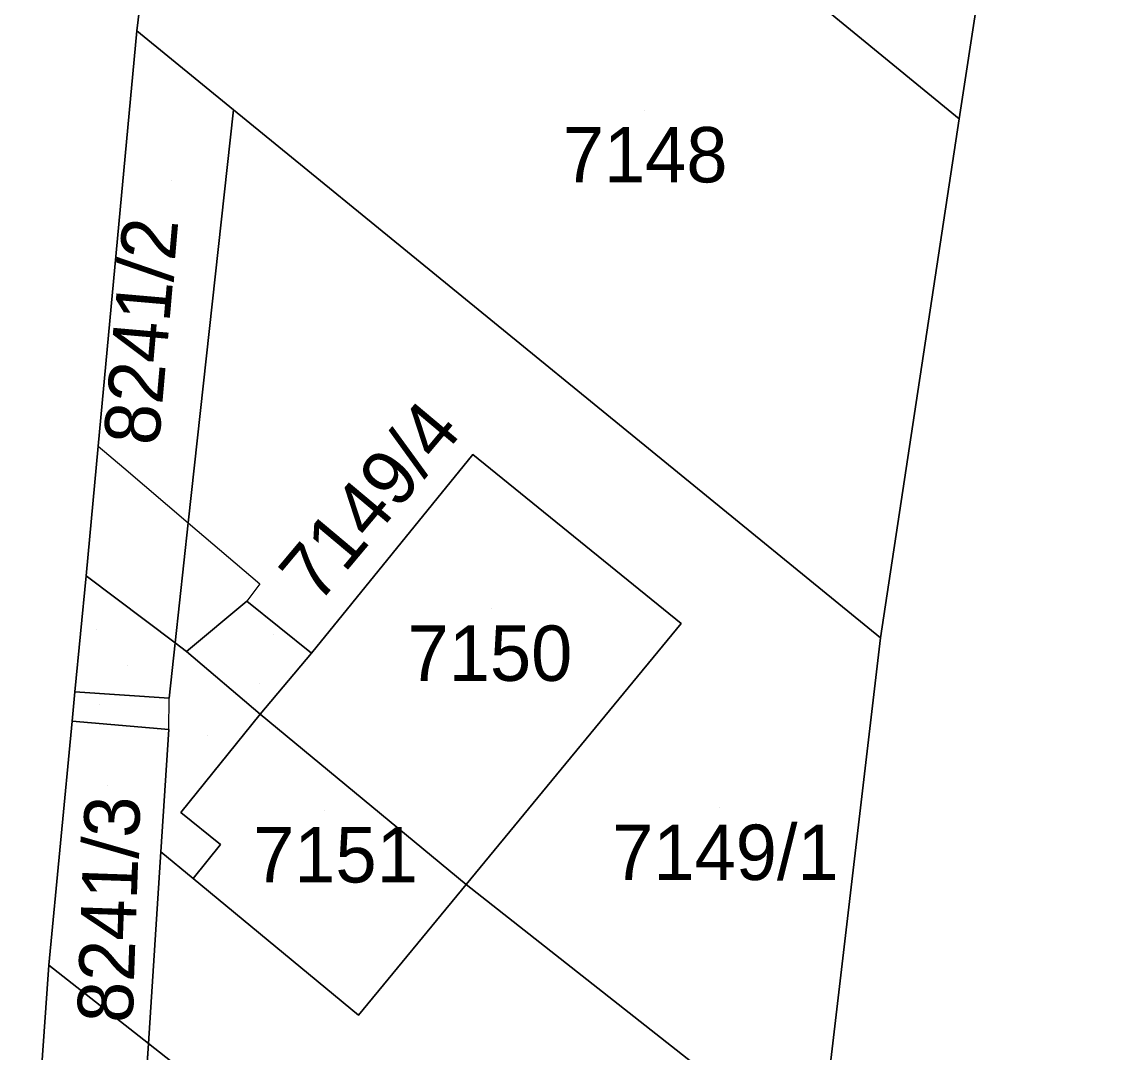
# Model space of a CAD drawing. Extents: x -266199 to -261993, y -1239047 to -1235108.
# Drawn here: x -263577.75 to -263537.93, y -1236344.71 to -1236307.48 of the extents above; entities that cross this region are included whole.
import ezdxf

# ---------------------------------------------------------------- set-up
doc = ezdxf.new("R2010")
doc.units = 0
for name, color, linetype in [('body_kn', 7, 'Continuous'), ('kladpar_druhypozemkov', 7, 'Continuous'), ('kladpar_hranice', 7, 'Continuous'), ('kladpar_parcelnecisla', 7, 'Continuous'), ('kladpar_plochy', 7, 'Continuous'), ('kladpar_sipky', 7, 'Continuous'), ('zappar_hrandruhpozemk', 7, 'Continuous')]:
    doc.layers.add(name, color=color, linetype=linetype)

msp = doc.modelspace()

# ---------------------------------------------------------------- linework, layer by layer
at = {"layer": 'body_kn'}
for p, q in [((-263573.6, -1236307.8), (-263573.6, -1236307.8)), ((-263570.11, -1236310.65), (-263570.11, -1236310.65)), ((-263570.11, -1236310.65), (-263570.11, -1236310.65)), ((-263543.91, -1236310.97), (-263543.91, -1236310.97)), ((-263543.91, -1236310.97), (-263543.91, -1236310.97)), ((-263575, -1236322.8), (-263575, -1236322.8)), ((-263575, -1236322.8), (-263575, -1236322.8)), ((-263561.47, -1236323.09), (-263561.47, -1236323.09)), ((-263574.08, -1236323.58), (-263574.08, -1236323.58)), ((-263571.75, -1236325.56), (-263571.75, -1236325.56)), ((-263571.75, -1236325.56), (-263571.75, -1236325.56)), ((-263575.44, -1236327.48), (-263575.44, -1236327.48)), ((-263575.44, -1236327.48), (-263575.44, -1236327.48)), ((-263569.16, -1236327.76), (-263569.16, -1236327.76)), ((-263569.63, -1236328.39), (-263569.63, -1236328.39)), ((-263553.95, -1236329.2), (-263553.95, -1236329.2)), ((-263572.22, -1236329.9), (-263572.22, -1236329.9)), ((-263546.75, -1236329.72), (-263546.75, -1236329.72)), ((-263546.75, -1236329.72), (-263546.75, -1236329.72)), ((-263571.81, -1236330.21), (-263571.81, -1236330.21)), ((-263571.81, -1236330.21), (-263571.81, -1236330.21)), ((-263567.3, -1236330.27), (-263567.3, -1236330.27)), ((-263575.84, -1236331.67), (-263575.84, -1236331.67)), ((-263575.84, -1236331.67), (-263575.84, -1236331.67)), ((-263572.44, -1236331.9), (-263572.44, -1236331.9)), ((-263572.44, -1236331.9), (-263572.44, -1236331.9)), ((-263575.94, -1236332.72), (-263575.94, -1236332.72)), ((-263575.94, -1236332.72), (-263575.94, -1236332.72)), ((-263569.15, -1236332.47), (-263569.15, -1236332.47)), ((-263569.15, -1236332.47), (-263569.15, -1236332.47)), ((-263572.45, -1236333.03), (-263572.45, -1236333.03)), ((-263572.45, -1236333.03), (-263572.45, -1236333.03)), ((-263572.02, -1236336.02), (-263572.02, -1236336.02)), ((-263570.58, -1236337.18), (-263570.58, -1236337.18)), ((-263572.74, -1236337.44), (-263572.74, -1236337.44)), ((-263571.57, -1236338.41), (-263571.57, -1236338.41)), ((-263561.71, -1236338.62), (-263561.71, -1236338.62)), ((-263561.71, -1236338.62), (-263561.71, -1236338.62)), ((-263576.78, -1236341.53), (-263576.78, -1236341.53)), ((-263576.78, -1236341.53), (-263576.78, -1236341.53)), ((-263565.6, -1236343.34), (-263565.6, -1236343.34)), ((-263565.6, -1236343.34), (-263565.6, -1236343.34)), ((-263573.19, -1236344.36), (-263573.19, -1236344.36)), ((-263573.19, -1236344.36), (-263573.19, -1236344.36))]:
    msp.add_line(p, q, dxfattribs=at)
at = {"layer": 'kladpar_druhypozemkov'}
for p, q in [((-263555.26, -1236310.67), (-263555.26, -1236310.67)), ((-263572.35, -1236313.2), (-263572.35, -1236313.2)), ((-263560.8, -1236328.67), (-263560.8, -1236328.67)), ((-263573.95, -1236330.71), (-263573.95, -1236330.71)), ((-263569.18, -1236331.37), (-263569.18, -1236331.37)), ((-263571.07, -1236333.24), (-263571.07, -1236333.24)), ((-263574.68, -1236335.06), (-263574.68, -1236335.06)), ((-263566.82, -1236335.95), (-263566.82, -1236335.95)), ((-263552.57, -1236335.86), (-263552.57, -1236335.86))]:
    msp.add_line(p, q, dxfattribs=at)
at = {"layer": 'kladpar_hranice'}
for p, q in [((-263570.11, -1236310.65), (-263546.75, -1236329.72)), ((-263572.22, -1236329.9), (-263575.44, -1236327.48)), ((-263572.22, -1236329.9), (-263572.44, -1236331.9)), ((-263572.44, -1236331.9), (-263572.22, -1236329.9)), ((-263572.44, -1236331.9), (-263575.84, -1236331.67)), ((-263574.1, -1236358.2), (-263573.19, -1236344.36))]:
    msp.add_line(p, q, dxfattribs=at)
for points in [[(-263558.35, -1236253.65), (-263562.84, -1236265.41), (-263567.17, -1236276.82), (-263569.75, -1236285.44), (-263570.76, -1236288.81), (-263572.25, -1236296.5), (-263572.6, -1236299.46), (-263573.6, -1236307.8), (-263575, -1236322.8), (-263575.44, -1236327.48), (-263575.84, -1236331.67), (-263575.94, -1236332.72), (-263576.78, -1236341.53), (-263577.75, -1236355.22)], [(-263543.62, -1236295.6), (-263544.64, -1236301.78), (-263542.57, -1236302.19), (-263543.91, -1236310.97), (-263559.34, -1236298.32), (-263557.89, -1236296.51), (-263556.7, -1236297.55), (-263551.42, -1236291.13), (-263556.42, -1236287.02)], [(-263569.54, -1236303.09), (-263564.68, -1236307.16), (-263561.84, -1236303.74), (-263563.04, -1236302.79), (-263559.34, -1236298.32), (-263543.91, -1236310.97)], [(-263543.91, -1236310.97), (-263546.75, -1236329.72), (-263570.11, -1236310.65), (-263573.6, -1236307.8), (-263572.6, -1236299.46)], [(-263548.98, -1236348.65), (-263546.75, -1236329.72), (-263543.91, -1236310.97), (-263542.57, -1236302.19), (-263537.88, -1236303.38), (-263527.86, -1236305.91), (-263519.85, -1236307.93), (-263521.69, -1236315.66), (-263522.6, -1236315.39), (-263523.06, -1236317.17), (-263522.12, -1236317.39), (-263523.87, -1236324.22), (-263526.33, -1236334.35), (-263527.51, -1236334.03), (-263527.95, -1236335.81), (-263526.76, -1236336.08), (-263528.55, -1236343.15), (-263530.96, -1236352.97)], [(-263575.44, -1236327.48), (-263575, -1236322.8), (-263573.6, -1236307.8), (-263570.11, -1236310.65)], [(-263572.22, -1236329.9), (-263571.75, -1236325.56), (-263570.11, -1236310.65)], [(-263570.11, -1236310.65), (-263571.75, -1236325.56), (-263572.22, -1236329.9)], [(-263546.75, -1236329.72), (-263548.98, -1236348.65), (-263561.71, -1236338.62), (-263553.95, -1236329.2), (-263561.47, -1236323.09), (-263567.3, -1236330.27), (-263569.63, -1236328.39), (-263571.81, -1236330.21), (-263572.22, -1236329.9)], [(-263569.15, -1236332.47), (-263567.3, -1236330.27), (-263561.47, -1236323.09), (-263553.95, -1236329.2), (-263561.71, -1236338.62), (-263569.15, -1236332.47)], [(-263575.84, -1236331.67), (-263575.44, -1236327.48), (-263572.22, -1236329.9)], [(-263571.81, -1236330.21), (-263569.63, -1236328.39), (-263567.3, -1236330.27), (-263569.15, -1236332.47), (-263571.81, -1236330.21)], [(-263572.22, -1236329.9), (-263571.81, -1236330.21), (-263569.15, -1236332.47), (-263572.02, -1236336.02), (-263570.58, -1236337.18), (-263571.57, -1236338.41), (-263572.74, -1236337.44), (-263572.45, -1236333.03), (-263575.94, -1236332.72)], [(-263575.94, -1236332.72), (-263575.84, -1236331.67), (-263572.44, -1236331.9)], [(-263576.78, -1236341.53), (-263575.94, -1236332.72), (-263572.45, -1236333.03), (-263572.74, -1236337.44), (-263573.19, -1236344.36), (-263576.78, -1236341.53)], [(-263565.6, -1236343.34), (-263571.57, -1236338.41), (-263570.58, -1236337.18), (-263572.02, -1236336.02), (-263569.15, -1236332.47), (-263561.71, -1236338.62), (-263565.6, -1236343.34)], [(-263561.71, -1236338.62), (-263548.98, -1236348.65), (-263550.58, -1236362.19), (-263573.19, -1236344.36), (-263572.74, -1236337.44), (-263571.57, -1236338.41), (-263565.6, -1236343.34), (-263561.71, -1236338.62)], [(-263577.75, -1236355.22), (-263576.78, -1236341.53), (-263573.19, -1236344.36), (-263574.1, -1236358.2), (-263577.75, -1236355.22)], [(-263573.19, -1236344.36), (-263550.58, -1236362.19), (-263551.73, -1236375.98), (-263563.49, -1236366.85), (-263559.86, -1236362.4), (-263558.79, -1236363.22), (-263555.92, -1236359.71), (-263565.8, -1236351.74), (-263568.67, -1236355.16)]]:
    msp.add_lwpolyline(points, dxfattribs=at)
at = {"layer": 'kladpar_plochy'}
for p, q in [((-263543.91, -1236310.97), (-263542.57, -1236302.19)), ((-263546.75, -1236329.72), (-263543.91, -1236310.97)), ((-263548.98, -1236348.65), (-263546.75, -1236329.72))]:
    msp.add_line(p, q, dxfattribs=at)
msp.add_lwpolyline([(-263558.35, -1236253.65), (-263562.84, -1236265.41), (-263567.17, -1236276.82), (-263569.75, -1236285.44), (-263570.76, -1236288.81), (-263572.25, -1236296.5), (-263572.6, -1236299.46), (-263573.6, -1236307.8), (-263575, -1236322.8), (-263575.44, -1236327.48), (-263575.84, -1236331.67), (-263575.94, -1236332.72), (-263576.78, -1236341.53), (-263577.75, -1236355.22)], dxfattribs=at)
for points in [[(-263543.62, -1236295.6), (-263544.64, -1236301.78), (-263542.57, -1236302.19), (-263543.91, -1236310.97), (-263559.34, -1236298.32), (-263557.89, -1236296.51), (-263556.7, -1236297.55), (-263551.42, -1236291.13), (-263556.42, -1236287.02), (-263569.75, -1236285.44), (-263567.17, -1236276.82)], [(-263543.91, -1236310.97), (-263546.75, -1236329.72), (-263570.11, -1236310.65), (-263573.6, -1236307.8), (-263572.6, -1236299.46), (-263569.54, -1236303.09), (-263564.68, -1236307.16), (-263561.84, -1236303.74), (-263563.04, -1236302.79), (-263559.34, -1236298.32)], [(-263575.44, -1236327.48), (-263575, -1236322.8), (-263573.6, -1236307.8), (-263570.11, -1236310.65), (-263571.75, -1236325.56), (-263572.22, -1236329.9)], [(-263546.75, -1236329.72), (-263548.98, -1236348.65), (-263561.71, -1236338.62), (-263553.95, -1236329.2), (-263561.47, -1236323.09), (-263567.3, -1236330.27), (-263569.63, -1236328.39), (-263571.81, -1236330.21), (-263572.22, -1236329.9), (-263571.75, -1236325.56), (-263570.11, -1236310.65)], [(-263569.15, -1236332.47), (-263567.3, -1236330.27), (-263561.47, -1236323.09), (-263553.95, -1236329.2), (-263561.71, -1236338.62)], [(-263575.84, -1236331.67), (-263575.44, -1236327.48), (-263572.22, -1236329.9), (-263572.44, -1236331.9)], [(-263571.81, -1236330.21), (-263569.63, -1236328.39), (-263567.3, -1236330.27), (-263569.15, -1236332.47)], [(-263575.94, -1236332.72), (-263575.84, -1236331.67), (-263572.44, -1236331.9), (-263572.22, -1236329.9), (-263571.81, -1236330.21), (-263569.15, -1236332.47), (-263572.02, -1236336.02), (-263570.58, -1236337.18), (-263571.57, -1236338.41), (-263572.74, -1236337.44), (-263572.45, -1236333.03)], [(-263576.78, -1236341.53), (-263575.94, -1236332.72), (-263572.45, -1236333.03), (-263572.74, -1236337.44), (-263573.19, -1236344.36)], [(-263565.6, -1236343.34), (-263571.57, -1236338.41), (-263570.58, -1236337.18), (-263572.02, -1236336.02), (-263569.15, -1236332.47), (-263561.71, -1236338.62)], [(-263561.71, -1236338.62), (-263548.98, -1236348.65), (-263550.58, -1236362.19), (-263573.19, -1236344.36), (-263572.74, -1236337.44), (-263571.57, -1236338.41), (-263565.6, -1236343.34)], [(-263577.75, -1236355.22), (-263576.78, -1236341.53), (-263573.19, -1236344.36), (-263574.1, -1236358.2)], [(-263573.19, -1236344.36), (-263550.58, -1236362.19), (-263551.73, -1236375.98), (-263563.49, -1236366.85), (-263559.86, -1236362.4), (-263558.79, -1236363.22), (-263555.92, -1236359.71), (-263565.8, -1236351.74), (-263568.67, -1236355.16), (-263569.95, -1236354.04), (-263573.66, -1236358.56), (-263574.1, -1236358.2)]]:
    msp.add_lwpolyline(points, close=True, dxfattribs=at)
at = {"layer": 'kladpar_sipky'}
for p, q in [((-263575.05, -1236329.42), (-263575.05, -1236329.42)), ((-263568.66, -1236329.58), (-263568.66, -1236329.58)), ((-263574.95, -1236332.13), (-263574.95, -1236332.13))]:
    msp.add_line(p, q, dxfattribs=at)
at = {"layer": 'zappar_hrandruhpozemk'}
for p, q in [((-263575, -1236322.8), (-263574.08, -1236323.58)), ((-263574.08, -1236323.58), (-263571.75, -1236325.56)), ((-263571.75, -1236325.56), (-263569.16, -1236327.76)), ((-263569.16, -1236327.76), (-263569.63, -1236328.39)), ((-263572.45, -1236333.03), (-263572.44, -1236331.9))]:
    msp.add_line(p, q, dxfattribs=at)

# ---------------------------------------------------------------- texts
at = {"layer": 'kladpar_parcelnecisla'}
for s, p in [('7148', (-263558.227, -1236313.27)), ('7150', (-263563.83, -1236331.27)), ('7149/1', (-263556.444, -1236338.46)), ('7151', (-263569.409, -1236338.55))]:
    msp.add_text(s, height=2, dxfattribs=at).set_placement(p)
for s, rotation, p in [('8241/2', 85, (-263572.819, -1236322.805)), ('7149/4', 50, (-263567.068, -1236328.548)), ('8241/3', 88, (-263573.763, -1236343.643))]:
    msp.add_text(s, height=2, rotation=rotation, dxfattribs=at).set_placement(p)

doc.saveas('drawing.dxf')
